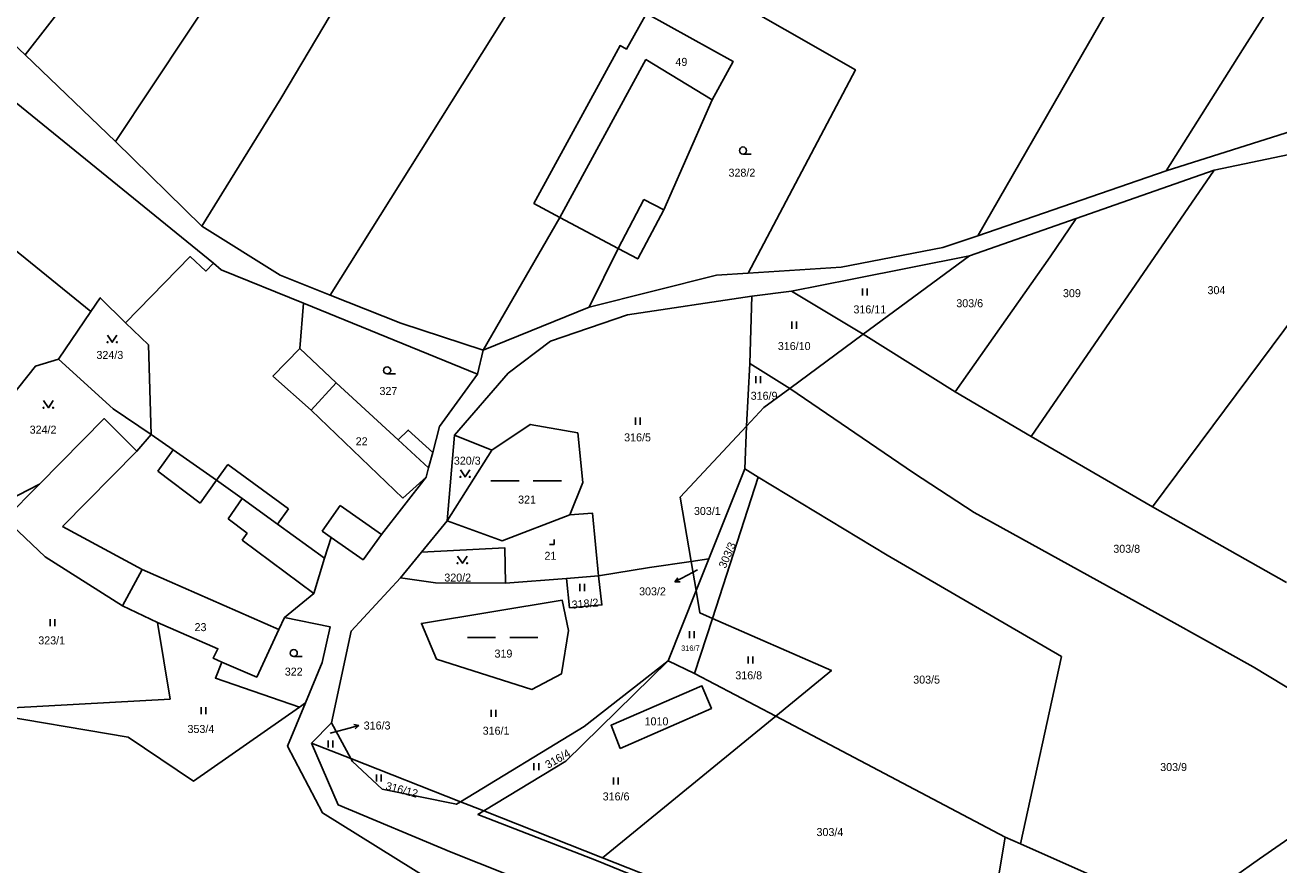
# Model space of a CAD drawing. Extents: x -751333 to -746055, y -1133395 to -1129777.
# Drawn here: x -747812.8 to -747546.5, y -1130823.7 to -1130645.3 of the extents above; entities that cross this region are included whole.
import ezdxf

# ---------------------------------------------------------------- set-up
doc = ezdxf.new("R2010")
doc.units = 0
for name, color, linetype in [('Hranice parcel', 7, 'Continuous'), ('Parcelní čísla', 7, 'Continuous'), ('Pop  PČ popisy', 7, 'Continuous'), ('Vnitřní kresba', 7, 'Continuous'), ('Značky kultur', 7, 'Continuous')]:
    doc.layers.add(name, color=color, linetype=linetype)

msp = doc.modelspace()

# ---------------------------------------------------------------- linework, layer by layer
at = {"layer": 'Hranice parcel'}
for p, q in [((-747793.6, -1130670.03), (-747812.8, -1130651.64)), ((-747855.76, -1130660), (-747798.81, -1130706.12)), ((-747775.28, -1130688.03), (-747793.6, -1130670.03)), ((-747570.47, -1130676.24), (-747610.44, -1130690.04)), ((-747560.26, -1130676.14), (-747599.16, -1130732.71)), ((-747589.6, -1130686.4), (-747560.26, -1130676.14)), ((-747699.24, -1130686.19), (-747715.52, -1130714.39)), ((-747612.23, -1130694.29), (-747589.6, -1130686.4)), ((-747693.04, -1130705.25), (-747686.87, -1130692.75)), ((-747612.23, -1130694.29), (-747634.84, -1130710.99)), ((-747658.86, -1130717.16), (-747658.46, -1130702.88)), ((-747658.46, -1130702.88), (-747650.07, -1130701.82)), ((-747634.84, -1130710.99), (-747650.07, -1130701.82)), ((-747798.81, -1130706.12), (-747805.74, -1130716.29)), ((-747716.72, -1130719.47), (-747753.68, -1130704.39)), ((-747715.52, -1130714.39), (-747693.04, -1130705.25)), ((-747634.84, -1130710.99), (-747650.43, -1130722.5)), ((-747634.84, -1130710.99), (-747615.28, -1130723.21)), ((-747715.52, -1130714.39), (-747716.72, -1130719.47)), ((-747659.58, -1130730.48), (-747658.86, -1130717.16)), ((-747650.43, -1130722.5), (-747658.86, -1130717.16)), ((-747599.16, -1130732.71), (-747615.28, -1130723.21)), ((-747721.58, -1130732.42), (-747723.2, -1130750.62)), ((-747713.69, -1130735.62), (-747721.58, -1130732.42)), ((-747659.94, -1130739.54), (-747659.58, -1130730.48)), ((-747573.4, -1130747.66), (-747599.16, -1130732.71)), ((-747723.2, -1130750.62), (-747713.69, -1130735.62)), ((-747667.62, -1130758.69), (-747659.94, -1130739.54)), ((-747657.09, -1130741.32), (-747659.94, -1130739.54)), ((-747809.75, -1130742.85), (-747826.34, -1130751.29)), ((-747666.84, -1130771.35), (-747657.09, -1130741.32)), ((-747544.95, -1130763.72), (-747573.4, -1130747.66)), ((-747723.2, -1130750.62), (-747728.64, -1130757.28)), ((-747728.64, -1130757.28), (-747733.07, -1130762.71)), ((-747671.35, -1130759.26), (-747667.62, -1130758.69)), ((-747670.31, -1130765.39), (-747671.35, -1130759.26)), ((-747670.31, -1130765.39), (-747667.62, -1130758.69)), ((-747710.78, -1130763.86), (-747697.84, -1130762.84)), ((-747697.84, -1130762.84), (-747691.02, -1130762.3)), ((-747676.24, -1130780.32), (-747670.31, -1130765.39)), ((-747670.62, -1130783), (-747666.84, -1130771.35)), ((-747670.62, -1130783), (-747676.24, -1130780.32)), ((-747653.39, -1130792.09), (-747670.62, -1130783)), ((-747754.53, -1130790.17), (-747753.28, -1130789.29)), ((-747751.97, -1130797.81), (-747747.71, -1130793.49)), ((-747747.71, -1130793.49), (-747743.6, -1130801.11)), ((-747653.39, -1130792.09), (-747690.17, -1130822.16)), ((-747604.68, -1130817.79), (-747653.39, -1130792.09)), ((-747743.6, -1130801.11), (-747751.97, -1130797.81)), ((-747743.6, -1130801.11), (-747720.35, -1130810.27)), ((-747715.36, -1130812.23), (-747720.35, -1130810.27)), ((-747715.36, -1130812.23), (-747690.17, -1130822.16)), ((-747604.68, -1130817.79), (-747601.44, -1130819.19)), ((-747567.45, -1130834.27), (-747601.44, -1130819.19)), ((-747690.17, -1130822.16), (-747619.1, -1130850.16))]:
    msp.add_line(p, q, dxfattribs=at)
for points in [[(-747670.88, -1130391.23), (-747687.06, -1130427.38), (-747690.77, -1130434.65), (-747700.47, -1130450.94), (-747706.19, -1130460.89), (-747729.37, -1130504.92), (-747757.72, -1130558.53), (-747788.4, -1130617.12), (-747798.54, -1130633.27), (-747812.8, -1130651.64)], [(-747640.79, -1130396.7), (-747657.25, -1130425.6), (-747681.35, -1130469.07), (-747696.46, -1130497.05), (-747715.13, -1130532.2), (-747745.26, -1130590.19), (-747770.48, -1130635.15), (-747793.6, -1130670.03)], [(-747623.29, -1130422.15), (-747647.06, -1130457.06), (-747666.03, -1130492.64), (-747685.16, -1130527.86), (-747701.96, -1130558.66), (-747718.97, -1130592.94), (-747735.96, -1130622.98), (-747758.49, -1130660.91), (-747775.28, -1130688.03)], [(-747406.55, -1130442.05), (-747433, -1130473.56), (-747450.34, -1130497.42), (-747482.92, -1130542.77), (-747509.09, -1130578.6), (-747506.37, -1130580.24), (-747519.16, -1130597.89), (-747541.31, -1130630.19), (-747554.26, -1130650.56), (-747570.47, -1130676.24)], [(-747610.44, -1130690.04), (-747588.32, -1130651.53), (-747569.82, -1130619.41), (-747553.67, -1130593.96), (-747509.74, -1130531.99), (-747495.01, -1130512.09), (-747487.14, -1130500.82)], [(-747659.21, -1130698.02), (-747636.48, -1130654.82), (-747696.45, -1130620.47), (-747747.98, -1130702.67)], [(-747812.8, -1130651.64), (-747826.2, -1130639.05), (-747848.84, -1130625.02)], [(-747854.2, -1130630.54), (-747821.59, -1130656.28), (-747772.81, -1130695.9)], [(-747686.87, -1130692.75), (-747682.7, -1130694.96), (-747677.13, -1130684.57), (-747666.92, -1130661.19), (-747662.42, -1130653.07), (-747680.82, -1130642.88), (-747685.09, -1130650.39), (-747686.45, -1130649.65), (-747704.74, -1130683.19), (-747699.24, -1130686.19)], [(-747527.24, -1130665.21), (-747542.3, -1130667.33), (-747570.47, -1130676.24)], [(-747513.08, -1130668.47), (-747532.69, -1130692.96), (-747573.4, -1130747.66)], [(-747560.26, -1130676.14), (-747530.15, -1130669.79), (-747513.08, -1130668.47)], [(-747615.28, -1130723.21), (-747595.09, -1130694.52), (-747589.6, -1130686.4)], [(-747775.28, -1130688.03), (-747758.65, -1130698.41), (-747747.98, -1130702.67)], [(-747659.21, -1130698.02), (-747639.49, -1130696.7), (-747617.92, -1130692.58), (-747610.44, -1130690.04)], [(-747772.81, -1130695.9), (-747774.39, -1130697.56), (-747777.71, -1130694.48), (-747791.49, -1130708.53)], [(-747650.07, -1130701.82), (-747637.16, -1130699.27), (-747612.23, -1130694.29)], [(-747753.68, -1130704.39), (-747771.13, -1130697.26), (-747772.81, -1130695.9)], [(-747693.04, -1130705.25), (-747665.96, -1130698.44), (-747659.21, -1130698.02)], [(-747791.49, -1130708.53), (-747796.84, -1130703.24), (-747798.81, -1130706.12)], [(-747747.98, -1130702.67), (-747732.98, -1130708.65), (-747715.52, -1130714.39)], [(-747721.58, -1130732.42), (-747710.19, -1130719.26), (-747701.22, -1130712.43), (-747684.85, -1130706.87), (-747658.46, -1130702.88)], [(-747726.24, -1130736.1), (-747731.42, -1130731.32), (-747733.56, -1130733.43), (-747746.76, -1130721.26), (-747754.46, -1130713.99), (-747753.68, -1130704.39)], [(-747791.49, -1130708.53), (-747786.57, -1130713.25), (-747786.02, -1130732.27)], [(-747805.74, -1130716.29), (-747810.6, -1130717.76), (-747823.18, -1130733.56)], [(-747786.02, -1130732.27), (-747794.12, -1130726.84), (-747805.74, -1130716.29)], [(-747726.24, -1130736.1), (-747724.79, -1130730.59), (-747716.72, -1130719.47)], [(-747650.43, -1130722.5), (-747655.93, -1130726.56), (-747659.58, -1130730.48)], [(-747650.43, -1130722.5), (-747624.13, -1130740.43), (-747611.24, -1130748.86), (-747568.75, -1130772.25), (-747551.99, -1130781.63), (-747518.4, -1130801.96)], [(-747786.02, -1130732.27), (-747789.07, -1130735.84), (-747796.03, -1130728.88), (-747809.75, -1130742.85)], [(-747697.09, -1130749.35), (-747694.34, -1130742.47), (-747695.42, -1130731.94), (-747705.51, -1130730.14), (-747713.69, -1130735.62)], [(-747786.02, -1130732.27), (-747781.34, -1130735.54), (-747772.13, -1130741.97), (-747766.72, -1130745.89), (-747759.19, -1130751.34), (-747749.2, -1130758.56)], [(-747659.58, -1130730.48), (-747673.66, -1130745.6), (-747671.35, -1130759.26)], [(-747749.2, -1130758.56), (-747747.81, -1130754.18), (-747741.04, -1130758.88), (-747737.14, -1130753.48), (-747727.62, -1130741.3), (-747727.11, -1130739.38), (-747726.24, -1130736.1)], [(-747809.75, -1130742.85), (-747817.01, -1130750.2), (-747808.52, -1130758.22), (-747792.09, -1130768.69), (-747784.71, -1130772.17)], [(-747601.44, -1130819.19), (-747592.67, -1130779.43), (-747629.73, -1130757.9), (-747657.09, -1130741.32)], [(-747697.09, -1130749.35), (-747711.49, -1130754.85), (-747723.2, -1130750.62)], [(-747691.02, -1130762.3), (-747692.31, -1130748.97), (-747697.09, -1130749.35)], [(-747728.64, -1130757.28), (-747710.89, -1130756.35), (-747710.78, -1130763.86)], [(-747757.69, -1130771.11), (-747751.51, -1130766.02), (-747749.2, -1130758.56)], [(-747671.35, -1130759.26), (-747680.2, -1130760.55), (-747691.02, -1130762.3)], [(-747733.07, -1130762.71), (-747743.57, -1130774.03), (-747747.71, -1130793.49)], [(-747710.78, -1130763.86), (-747725.61, -1130763.78), (-747733.07, -1130762.71)], [(-747691.02, -1130762.3), (-747690.32, -1130768.47), (-747697.18, -1130769.08), (-747697.84, -1130762.84)], [(-747697.37, -1130773.87), (-747698.91, -1130783.11), (-747705.17, -1130786.4), (-747725.4, -1130779.97), (-747728.64, -1130772.38), (-747698.74, -1130767.49), (-747697.37, -1130773.87)], [(-747670.31, -1130765.39), (-747669.5, -1130770.18), (-747666.84, -1130771.35)], [(-747822, -1130790.67), (-747782.01, -1130788.46), (-747784.71, -1130772.17)], [(-747784.71, -1130772.17), (-747771.86, -1130777.78), (-747772.86, -1130779.79), (-747771.01, -1130780.65)], [(-747771.01, -1130780.65), (-747763.61, -1130783.79), (-747758.9, -1130773.71), (-747757.69, -1130771.11)], [(-747753.28, -1130789.29), (-747749.73, -1130780.72), (-747748, -1130773.12), (-747757.69, -1130771.11)], [(-747666.84, -1130771.35), (-747641.57, -1130782.42), (-747653.39, -1130792.09)], [(-747771.01, -1130780.65), (-747772.38, -1130784.02), (-747754.53, -1130790.17)], [(-747720.35, -1130810.27), (-747694.06, -1130794.29), (-747676.24, -1130780.32)], [(-747715.36, -1130812.23), (-747697.97, -1130801.66), (-747676.24, -1130780.32)], [(-747686.45, -1130798.94), (-747688.36, -1130794.01), (-747669.08, -1130785.64), (-747667.06, -1130790.44), (-747686.45, -1130798.94)], [(-747754.53, -1130790.17), (-747777.03, -1130805.89), (-747790.88, -1130796.57), (-747821.89, -1130791.29), (-747822, -1130790.67)], [(-747726.57, -1130826.97), (-747749.62, -1130812.66), (-747757.07, -1130798.44), (-747753.28, -1130789.29)], [(-747751.97, -1130797.81), (-747746.34, -1130810.93), (-747722.32, -1130820.98), (-747692.92, -1130832.64)], [(-747720.35, -1130810.27), (-747721.21, -1130810.79), (-747736.95, -1130807.6), (-747743.26, -1130801.74), (-747743.6, -1130801.11)], [(-747518.4, -1130801.96), (-747535.86, -1130812.1), (-747550.62, -1130822.39), (-747567.45, -1130834.27)], [(-747619.1, -1130850.16), (-747638.4, -1130850.1), (-747647.23, -1130843.67), (-747648.62, -1130840.27), (-747691.42, -1130822.76), (-747716.64, -1130813.01), (-747715.36, -1130812.23)], [(-747619.1, -1130850.16), (-747610.15, -1130850.19), (-747604.68, -1130817.79)]]:
    msp.add_lwpolyline(points, dxfattribs=at)
at = {"layer": 'Pop  PČ popisy'}
for p, q in [((-747672.16, -1130762.18), (-747674.81, -1130763.589)), ((-747670, -1130761.02), (-747672.16, -1130762.18)), ((-747674.81, -1130763.589), (-747674.161, -1130762.677)), ((-747674.81, -1130763.589), (-747673.69, -1130763.561)), ((-747744.79, -1130794.83), (-747741.891, -1130794.053)), ((-747741.891, -1130794.053), (-747742.988, -1130793.829)), ((-747741.891, -1130794.053), (-747742.729, -1130794.796)), ((-747748.01, -1130795.67), (-747744.79, -1130794.83))]:
    msp.add_line(p, q, dxfattribs=at)
at = {"layer": 'Vnitřní kresba'}
for p, q in [((-747680.95, -1130652.65), (-747699.24, -1130686.19)), ((-747680.95, -1130652.65), (-747666.92, -1130661.19)), ((-747686.87, -1130692.75), (-747681.37, -1130682.37)), ((-747681.37, -1130682.37), (-747677.13, -1130684.57)), ((-747686.87, -1130692.75), (-747699.24, -1130686.19)), ((-747760.16, -1130719.86), (-747754.46, -1130713.99)), ((-747752.04, -1130727.1), (-747760.16, -1130719.86)), ((-747752.04, -1130727.1), (-747746.76, -1130721.26)), ((-747732.61, -1130745.77), (-747752.04, -1130727.1)), ((-747784.64, -1130740.08), (-747781.34, -1130735.54)), ((-747733.56, -1130733.43), (-747727.11, -1130739.38)), ((-747804.85, -1130751.83), (-747789.07, -1130735.84)), ((-747784.64, -1130740.08), (-747775.61, -1130746.82)), ((-747772.13, -1130741.97), (-747769.75, -1130738.64)), ((-747769.75, -1130738.64), (-747756.83, -1130748.04)), ((-747775.61, -1130746.82), (-747772.13, -1130741.97)), ((-747727.62, -1130741.3), (-747732.61, -1130745.77)), ((-747766.72, -1130745.89), (-747769.69, -1130750.15)), ((-747756.83, -1130748.04), (-747759.19, -1130751.34)), ((-747749.74, -1130752.83), (-747745.91, -1130747.32)), ((-747745.91, -1130747.32), (-747737.14, -1130753.48)), ((-747769.69, -1130750.15), (-747765.62, -1130753.26)), ((-747787.96, -1130760.97), (-747804.85, -1130751.83)), ((-747765.62, -1130753.26), (-747766.67, -1130754.69)), ((-747747.81, -1130754.18), (-747749.74, -1130752.83)), ((-747766.67, -1130754.69), (-747751.51, -1130766.02)), ((-747792.09, -1130768.69), (-747787.96, -1130760.97)), ((-747787.96, -1130760.97), (-747758.9, -1130773.71))]:
    msp.add_line(p, q, dxfattribs=at)
at = {"layer": 'Značky kultur'}
for p, q in [((-747660.343, -1130672.7), (-747658.593, -1130672.7)), ((-747634.971, -1130702.76), (-747634.971, -1130701.26)), ((-747633.97, -1130702.76), (-747633.97, -1130701.26)), ((-747649.971, -1130709.8), (-747649.971, -1130708.3)), ((-747648.97, -1130709.8), (-747648.97, -1130708.3)), ((-747735.913, -1130719.4), (-747734.163, -1130719.4)), ((-747657.611, -1130721.37), (-747657.611, -1130719.87)), ((-747656.61, -1130721.37), (-747656.61, -1130719.87)), ((-747683.151, -1130730.18), (-747683.151, -1130728.68)), ((-747682.15, -1130730.18), (-747682.15, -1130728.68)), ((-747713.869, -1130742.11), (-747707.869, -1130742.11)), ((-747704.869, -1130742.11), (-747698.869, -1130742.11)), ((-747701.431, -1130755.6), (-747700.43, -1130755.6)), ((-747700.43, -1130755.6), (-747700.43, -1130754.6)), ((-747695.021, -1130765.52), (-747695.021, -1130764.02)), ((-747694.02, -1130765.52), (-747694.02, -1130764.02)), ((-747807.481, -1130772.98), (-747807.481, -1130771.48)), ((-747806.48, -1130772.98), (-747806.48, -1130771.48)), ((-747718.879, -1130775.35), (-747712.879, -1130775.35)), ((-747709.879, -1130775.35), (-747703.879, -1130775.35)), ((-747671.681, -1130775.56), (-747671.681, -1130774.06)), ((-747670.68, -1130775.56), (-747670.68, -1130774.06)), ((-747755.743, -1130779.44), (-747753.993, -1130779.44)), ((-747659.251, -1130780.9), (-747659.251, -1130779.4)), ((-747658.25, -1130780.9), (-747658.25, -1130779.4)), ((-747775.411, -1130791.65), (-747775.411, -1130790.15)), ((-747774.41, -1130791.65), (-747774.41, -1130790.15)), ((-747713.821, -1130792.27), (-747713.821, -1130790.77)), ((-747712.82, -1130792.27), (-747712.82, -1130790.77)), ((-747748.421, -1130798.77), (-747748.421, -1130797.27)), ((-747747.42, -1130798.77), (-747747.42, -1130797.27)), ((-747704.731, -1130803.55), (-747704.731, -1130802.05)), ((-747703.73, -1130803.55), (-747703.73, -1130802.05)), ((-747738.161, -1130805.95), (-747738.161, -1130804.45)), ((-747737.16, -1130805.95), (-747737.16, -1130804.45)), ((-747687.861, -1130806.62), (-747687.861, -1130805.12)), ((-747686.86, -1130806.62), (-747686.86, -1130805.12))]:
    msp.add_line(p, q, dxfattribs=at)
for points in [[(-747795.3, -1130711.169), (-747794.3, -1130712.67), (-747793.3, -1130711.169)], [(-747808.86, -1130725.079), (-747807.86, -1130726.58), (-747806.86, -1130725.079)], [(-747720.36, -1130739.789), (-747719.36, -1130741.29), (-747718.36, -1130739.789)], [(-747720.94, -1130758.109), (-747719.94, -1130759.61), (-747718.94, -1130758.109)]]:
    msp.add_lwpolyline(points, dxfattribs=at)
for centre, radius in [((-747660.343, -1130671.95), 0.75), ((-747795.3, -1130712.669), 0.1), ((-747793.3, -1130712.669), 0.1), ((-747735.913, -1130718.65), 0.75), ((-747808.86, -1130726.579), 0.1), ((-747806.86, -1130726.579), 0.1), ((-747720.36, -1130741.289), 0.1), ((-747718.36, -1130741.289), 0.1), ((-747720.94, -1130759.609), 0.1), ((-747718.94, -1130759.609), 0.1), ((-747755.743, -1130778.69), 0.75)]:
    msp.add_circle(centre, radius, dxfattribs=at)

# ---------------------------------------------------------------- texts
at = {"layer": 'Parcelní čísla'}
for s, height, p in [('49', 1.7, (-747674.69, -1130653.97)), ('328/2', 1.7, (-747663.42, -1130677.51)), ('304', 1.7, (-747561.69, -1130702.46)), ('303/6', 1.7, (-747615.04, -1130705.24)), ('309', 1.7, (-747592.39, -1130703.1)), ('316/11', 1.7, (-747636.89, -1130706.55)), ('316/10', 1.7, (-747652.94, -1130714.33)), ('324/3', 1.7, (-747797.65, -1130716.22)), ('327', 1.7, (-747737.54, -1130723.88)), ('316/9', 1.7, (-747658.71, -1130724.89)), ('324/2', 1.7, (-747811.83, -1130732.09)), ('22', 1.7, (-747742.59, -1130734.56)), ('316/5', 1.7, (-747685.58, -1130733.73)), ('320/3', 1.7, (-747721.75, -1130738.68)), ('321', 1.7, (-747708.1, -1130746.94)), ('303/1', 1.7, (-747670.76, -1130749.36)), ('303/8', 1.7, (-747581.7, -1130757.39)), ('21', 1.7, (-747702.506, -1130758.88)), ('320/2', 1.7, (-747723.77, -1130763.51)), ('303/2', 1.7, (-747682.407, -1130766.438)), ('23', 1.7, (-747776.81, -1130774.03)), ('323/1', 1.7, (-747810, -1130776.85)), ('319', 1.7, (-747713.11, -1130779.65)), ('316/7', 1.14, (-747673.48, -1130778.22)), ('322', 1.7, (-747757.65, -1130783.48)), ('316/8', 1.7, (-747661.97, -1130784.27)), ('303/5', 1.7, (-747624.19, -1130785.18)), ('353/4', 1.7, (-747778.31, -1130795.66)), ('316/3', 1.7, (-747740.89, -1130794.93)), ('1010', 1.7, (-747681.244, -1130794.05)), ('316/1', 1.7, (-747715.63, -1130796.03)), ('303/9', 1.7, (-747571.74, -1130803.75)), ('316/6', 1.7, (-747690.14, -1130809.99)), ('303/4', 1.7, (-747644.73, -1130817.56))]:
    msp.add_text(s, height=height, dxfattribs=at).set_placement(p)
for s, rotation, p in [('303/3', 67, (-747664.027, -1130760.832)), ('318/2', 5, (-747696.635, -1130769.276)), ('316/4', 30, (-747701.735, -1130803.306)), ('316/12', 345, (-747736.369, -1130807.641))]:
    msp.add_text(s, height=1.7, rotation=rotation, dxfattribs=at).set_placement(p)

doc.saveas('drawing.dxf')
